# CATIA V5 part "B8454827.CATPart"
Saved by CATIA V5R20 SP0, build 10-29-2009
Part number: B8454827
Revision: 3
Definition: design
Nomenclature: B8454827
Source: made
Description: NOT SPECIFIED
Bounding box of the stored display mesh (mm): x -36.5 to 36.5, y -36.5 to 36.5, z -27 to 36
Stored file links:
  C:\Users\Utente\Desktop\3D files B845\B8454827.CATPart
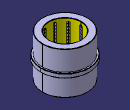
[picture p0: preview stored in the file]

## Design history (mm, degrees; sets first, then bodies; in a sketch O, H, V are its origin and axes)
Body1 "MANIFOLD_SOLID_BREP #38" (main body)
  Solid1: solid without history
Body2 "MANIFOLD_SOLID_BREP #2506"
  Solid2: solid without history
Body3 "MANIFOLD_SOLID_BREP #2544"
  Solid3: solid without history
Body4 "MANIFOLD_SOLID_BREP #2582"
  Solid4: solid without history
Body5 "MANIFOLD_SOLID_BREP #2620"
  Solid5: solid without history
Body6 "MANIFOLD_SOLID_BREP #2658"
  Solid6: solid without history
Body7 "MANIFOLD_SOLID_BREP #2696"
  Solid7: solid without history
Body8 "MANIFOLD_SOLID_BREP #2734"
  Solid8: solid without history
Body9 "MANIFOLD_SOLID_BREP #2772"
  Solid9: solid without history
Body10 "MANIFOLD_SOLID_BREP #2810"
  Solid10: solid without history
Body11 "MANIFOLD_SOLID_BREP #2848"
  Solid11: solid without history
Body12 "MANIFOLD_SOLID_BREP #2886"
  Solid12: solid without history
Body13 "MANIFOLD_SOLID_BREP #2924"
  Solid13: solid without history
Body14 "MANIFOLD_SOLID_BREP #2962"
  Solid14: solid without history
Body15 "MANIFOLD_SOLID_BREP #3000"
  Solid15: solid without history
Body16 "MANIFOLD_SOLID_BREP #3038"
  Solid16: solid without history
Body17 "MANIFOLD_SOLID_BREP #3076"
  Solid17: solid without history
Body18 "MANIFOLD_SOLID_BREP #3114"
  Solid18: solid without history
Body19 "MANIFOLD_SOLID_BREP #3152"
  Solid19: solid without history
Body20 "MANIFOLD_SOLID_BREP #3190"
  Solid20: solid without history
Body21 "MANIFOLD_SOLID_BREP #3228"
  Solid21: solid without history
Body22 "MANIFOLD_SOLID_BREP #3266"
  Solid22: solid without history
Body23 "MANIFOLD_SOLID_BREP #3304"
  Solid23: solid without history
Body24 "MANIFOLD_SOLID_BREP #3342"
  Solid24: solid without history
Body25 "MANIFOLD_SOLID_BREP #3380"
  Solid25: solid without history
Body26 "MANIFOLD_SOLID_BREP #3418"
  Solid26: solid without history
Body27 "MANIFOLD_SOLID_BREP #3456"
  Solid27: solid without history
Body28 "MANIFOLD_SOLID_BREP #3494"
  Solid28: solid without history
Body29 "MANIFOLD_SOLID_BREP #3532"
  Solid29: solid without history
Body30 "MANIFOLD_SOLID_BREP #3570"
  Solid30: solid without history
Body31 "MANIFOLD_SOLID_BREP #3608"
  Solid31: solid without history
Body32 "MANIFOLD_SOLID_BREP #3646"
  Solid32: solid without history
Body33 "MANIFOLD_SOLID_BREP #3684"
  Solid33: solid without history
Body34 "MANIFOLD_SOLID_BREP #3722"
  Solid34: solid without history
Body35 "MANIFOLD_SOLID_BREP #3760"
  Solid35: solid without history
Body36 "MANIFOLD_SOLID_BREP #3798"
  Solid36: solid without history
Body37 "MANIFOLD_SOLID_BREP #3836"
  Solid37: solid without history
Body38 "MANIFOLD_SOLID_BREP #3874"
  Solid38: solid without history
Body39 "MANIFOLD_SOLID_BREP #3912"
  Solid39: solid without history
Body40 "MANIFOLD_SOLID_BREP #3950"
  Solid40: solid without history
Body41 "MANIFOLD_SOLID_BREP #3988"
  Solid41: solid without history
Body42 "MANIFOLD_SOLID_BREP #4026"
  Solid42: solid without history
Body43 "MANIFOLD_SOLID_BREP #4064"
  Solid43: solid without history
Body44 "MANIFOLD_SOLID_BREP #4102"
  Solid44: solid without history
Body45 "MANIFOLD_SOLID_BREP #4140"
  Solid45: solid without history
Body46 "MANIFOLD_SOLID_BREP #4178"
  Solid46: solid without history
Body47 "MANIFOLD_SOLID_BREP #4216"
  Solid47: solid without history
Body48 "MANIFOLD_SOLID_BREP #4254"
  Solid48: solid without history
Body49 "MANIFOLD_SOLID_BREP #4292"
  Solid49: solid without history
Body50 "MANIFOLD_SOLID_BREP #4330"
  Solid50: solid without history
Body51 "MANIFOLD_SOLID_BREP #4368"
  Solid51: solid without history
Body52 "MANIFOLD_SOLID_BREP #4406"
  Solid52: solid without history
Body53 "MANIFOLD_SOLID_BREP #4444"
  Solid53: solid without history
Body54 "MANIFOLD_SOLID_BREP #4482"
  Solid54: solid without history
Body55 "MANIFOLD_SOLID_BREP #4520"
  Solid55: solid without history
Body56 "MANIFOLD_SOLID_BREP #4558"
  Solid56: solid without history
Body57 "MANIFOLD_SOLID_BREP #4596"
  Solid57: solid without history
Body58 "MANIFOLD_SOLID_BREP #4634"
  Solid58: solid without history
Body59 "MANIFOLD_SOLID_BREP #4672"
  Solid59: solid without history
Body60 "MANIFOLD_SOLID_BREP #4710"
  Solid60: solid without history
Body61 "MANIFOLD_SOLID_BREP #4748"
  Solid61: solid without history
Body62 "MANIFOLD_SOLID_BREP #4786"
  Solid62: solid without history
Body63 "MANIFOLD_SOLID_BREP #4824"
  Solid63: solid without history
Body64 "MANIFOLD_SOLID_BREP #4862"
  Solid64: solid without history
Body65 "MANIFOLD_SOLID_BREP #4900"
  Solid65: solid without history
Body66 "MANIFOLD_SOLID_BREP #4938"
  Solid66: solid without history
Body67 "MANIFOLD_SOLID_BREP #4976"
  Solid67: solid without history
Body68 "MANIFOLD_SOLID_BREP #5014"
  Solid68: solid without history
Body69 "MANIFOLD_SOLID_BREP #5052"
  Solid69: solid without history
Body70 "MANIFOLD_SOLID_BREP #5090"
  Solid70: solid without history
Body71 "MANIFOLD_SOLID_BREP #5128"
  Solid71: solid without history
Body72 "MANIFOLD_SOLID_BREP #5166"
  Solid72: solid without history
Body73 "MANIFOLD_SOLID_BREP #5204"
  Solid73: solid without history
Body74 "MANIFOLD_SOLID_BREP #5242"
  Solid74: solid without history
Body75 "MANIFOLD_SOLID_BREP #5280"
  Solid75: solid without history
Body76 "MANIFOLD_SOLID_BREP #5318"
  Solid76: solid without history
Body77 "MANIFOLD_SOLID_BREP #5356"
  Solid77: solid without history
Body78 "MANIFOLD_SOLID_BREP #5394"
  Solid78: solid without history
Body79 "MANIFOLD_SOLID_BREP #5432"
  Solid79: solid without history
Body80 "MANIFOLD_SOLID_BREP #5470"
  Solid80: solid without history
Body81 "MANIFOLD_SOLID_BREP #5508"
  Solid81: solid without history
Body82 "MANIFOLD_SOLID_BREP #5546"
  Solid82: solid without history
Body83 "MANIFOLD_SOLID_BREP #5584"
  Solid83: solid without history
Body84 "MANIFOLD_SOLID_BREP #5622"
  Solid84: solid without history
Body85 "MANIFOLD_SOLID_BREP #5660"
  Solid85: solid without history
Body86 "MANIFOLD_SOLID_BREP #5698"
  Solid86: solid without history
Body87 "MANIFOLD_SOLID_BREP #5736"
  Solid87: solid without history
Body88 "MANIFOLD_SOLID_BREP #5774"
  Solid88: solid without history
Body89 "MANIFOLD_SOLID_BREP #5812"
  Solid89: solid without history
Body90 "MANIFOLD_SOLID_BREP #5850"
  Solid90: solid without history
Body91 "MANIFOLD_SOLID_BREP #5888"
  Solid91: solid without history
Body92 "MANIFOLD_SOLID_BREP #5926"
  Solid92: solid without history
Body93 "MANIFOLD_SOLID_BREP #5964"
  Solid93: solid without history
Body94 "MANIFOLD_SOLID_BREP #6002"
  Solid94: solid without history
Body95 "MANIFOLD_SOLID_BREP #6040"
  Solid95: solid without history
Body96 "MANIFOLD_SOLID_BREP #6078"
  Solid96: solid without history
Body97 "MANIFOLD_SOLID_BREP #6116"
  Solid97: solid without history
Body98 "MANIFOLD_SOLID_BREP #6154"
  Solid98: solid without history
Body99 "MANIFOLD_SOLID_BREP #6192"
  Solid99: solid without history
Body100 "MANIFOLD_SOLID_BREP #6230"
  Solid100: solid without history
Body101 "MANIFOLD_SOLID_BREP #6268"
  Solid101: solid without history
Body102 "MANIFOLD_SOLID_BREP #6306"
  Solid102: solid without history
Body103 "MANIFOLD_SOLID_BREP #6344"
  Solid103: solid without history
Body104 "MANIFOLD_SOLID_BREP #6382"
  Solid104: solid without history
Body105 "MANIFOLD_SOLID_BREP #6420"
  Solid105: solid without history
Body106 "MANIFOLD_SOLID_BREP #6458"
  Solid106: solid without history
Body107 "MANIFOLD_SOLID_BREP #6496"
  Solid107: solid without history
Body108 "MANIFOLD_SOLID_BREP #6534"
  Solid108: solid without history
Body109 "MANIFOLD_SOLID_BREP #6572"
  Solid109: solid without history
Body110 "MANIFOLD_SOLID_BREP #6610"
  Solid110: solid without history
Body111 "MANIFOLD_SOLID_BREP #6648"
  Solid111: solid without history
Body112 "MANIFOLD_SOLID_BREP #6686"
  Solid112: solid without history
Body113 "MANIFOLD_SOLID_BREP #6724"
  Solid113: solid without history
Body114 "MANIFOLD_SOLID_BREP #6762"
  Solid114: solid without history
Body115 "MANIFOLD_SOLID_BREP #6800"
  Solid115: solid without history
Body116 "MANIFOLD_SOLID_BREP #6838"
  Solid116: solid without history
Body117 "MANIFOLD_SOLID_BREP #6876"
  Solid117: solid without history
Body118 "MANIFOLD_SOLID_BREP #6914"
  Solid118: solid without history
Body119 "MANIFOLD_SOLID_BREP #6952"
  Solid119: solid without history
Body120 "MANIFOLD_SOLID_BREP #6990"
  Solid120: solid without history
Body121 "MANIFOLD_SOLID_BREP #7028"
  Solid121: solid without history
Body122 "MANIFOLD_SOLID_BREP #7066"
  Solid122: solid without history
Body123 "MANIFOLD_SOLID_BREP #7104"
  Solid123: solid without history
Body124 "MANIFOLD_SOLID_BREP #7142"
  Solid124: solid without history
Body125 "MANIFOLD_SOLID_BREP #7180"
  Solid125: solid without history
Body126 "MANIFOLD_SOLID_BREP #7218"
  Solid126: solid without history
Body127 "MANIFOLD_SOLID_BREP #7256"
  Solid127: solid without history
Body128 "MANIFOLD_SOLID_BREP #7294"
  Solid128: solid without history
Body129 "MANIFOLD_SOLID_BREP #7332"
  Solid129: solid without history
Body130 "MANIFOLD_SOLID_BREP #7370"
  Solid130: solid without history
Body131 "MANIFOLD_SOLID_BREP #7408"
  Solid131: solid without history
